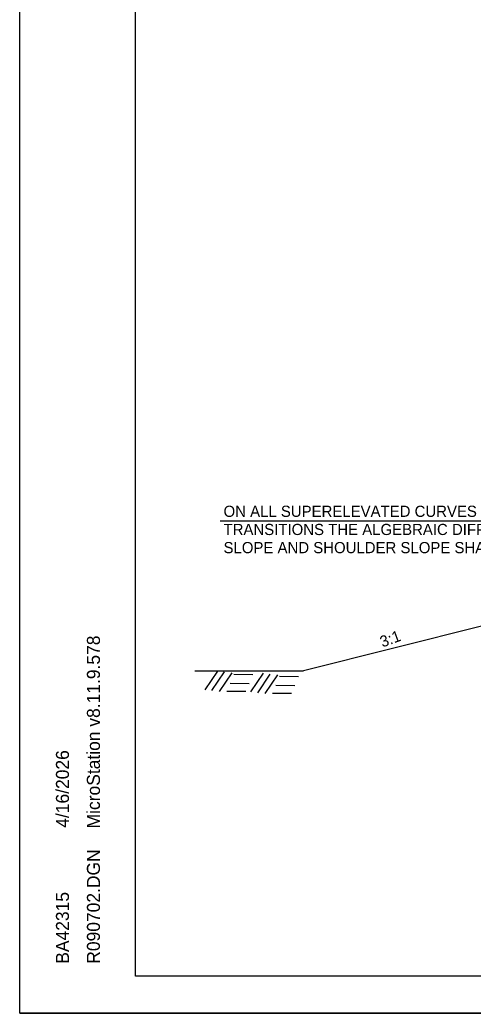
# Model space of a CAD drawing. Extents: x 1371763 to 1372860, y 385599 to 385872.
# Drawn here: x 1372493 to 1372517.3, y 385598.6 to 385651.9 of the extents above; entities that cross this region are included whole.
import ezdxf

# ---------------------------------------------------------------- set-up
doc = ezdxf.new("R2010")
doc.units = 0
for name, color, linetype in [('R_Border', 7, 'Continuous'), ('R_Draft', 7, 'Continuous'), ('R_Fin Surface', 7, 'Continuous'), ('R_No Plot', 7, 'Continuous')]:
    doc.layers.add(name, color=color, linetype=linetype)

msp = doc.modelspace()

# ---------------------------------------------------------------- linework, layer by layer
at = {"layer": 'R_Border'}
for p, q in [((1372499.208, 385600.577), (1372499.208, 385703.307)), ((1372499.208, 385600.577), (1372499.208, 385600.577)), ((1372657.298, 385600.577), (1372499.208, 385600.577))]:
    msp.add_line(p, q, dxfattribs=at)
at = {"layer": 'R_Draft'}
for p, q in [((1372503.754, 385625.023), (1372532.427, 385625.023)), ((1372517.923, 385619.399), (1372508.221, 385616.974)), ((1372502.957, 385615.943), (1372503.633, 385616.944)), ((1372503.316, 385615.901), (1372503.991, 385616.903)), ((1372503.716, 385615.859), (1372504.392, 385616.861)), ((1372504.492, 385616.786), (1372505.51, 385616.777)), ((1372505.41, 385615.834), (1372506.086, 385616.836)), ((1372505.769, 385615.793), (1372506.444, 385616.794)), ((1372504.292, 385616.302), (1372505.31, 385616.293)), ((1372506.169, 385615.751), (1372506.845, 385616.752)), ((1372506.945, 385616.677), (1372507.963, 385616.669)), ((1372504.117, 385615.876), (1372505.134, 385615.868)), ((1372506.569, 385615.767), (1372507.587, 385615.759)), ((1372506.745, 385616.193), (1372507.762, 385616.185))]:
    msp.add_line(p, q, dxfattribs=at)
at = {"layer": 'R_Fin Surface'}
msp.add_line((1372502.404, 385616.974), (1372508.221, 385616.974), dxfattribs=at)
at = {"layer": 'R_No Plot'}
msp.add_line((1372493.007, 385598.587), (1372659.674, 385598.587), dxfattribs=at)
for points in [[(1372493.004, 385705.254), (1372659.674, 385705.254), (1372659.674, 385598.585), (1372493.004, 385598.585)], [(1372616.168, 385703.307), (1372625.978, 385703.307), (1372625.978, 385698.367), (1372634.034, 385698.367), (1372645.634, 385698.367), (1372645.634, 385682.032), (1372657.238, 385682.032), (1372657.298, 385600.577), (1372499.208, 385600.577), (1372499.208, 385703.307)]]:
    msp.add_lwpolyline(points, close=True, dxfattribs=at)

# ---------------------------------------------------------------- texts
at = {"layer": 'R_Border'}
for s, p in [('MicroStation v8.11.9.578', (1372497.303, 385608.505)), ('4/16/2026', (1372495.64, 385608.54)), ('R090702.DGN', (1372497.303, 385601.239)), ('BA42315', (1372495.64, 385601.239))]:
    msp.add_text(s, height=0.7, rotation=90, dxfattribs=at).set_placement(p)
at = {"layer": 'R_Draft'}
for s, p in [('ON ALL SUPERELEVATED CURVES AND THRU SUPERELEVATION', (1372503.937, 385625.232)), ('TRANSITIONS THE ALGEBRAIC DIFFERENCE BETWEEN PAVEMENT', (1372503.937, 385624.257)), ("SLOPE AND SHOULDER SLOPE SHALL NOT EXCEED 0.08'/'", (1372503.937, 385623.282))]:
    msp.add_text(s, height=0.6, dxfattribs=at).set_placement(p)
msp.add_text('3:1', height=0.6, rotation=19.9978, dxfattribs=at).set_placement((1372512.463, 385618.216))

doc.saveas('drawing.dxf')
